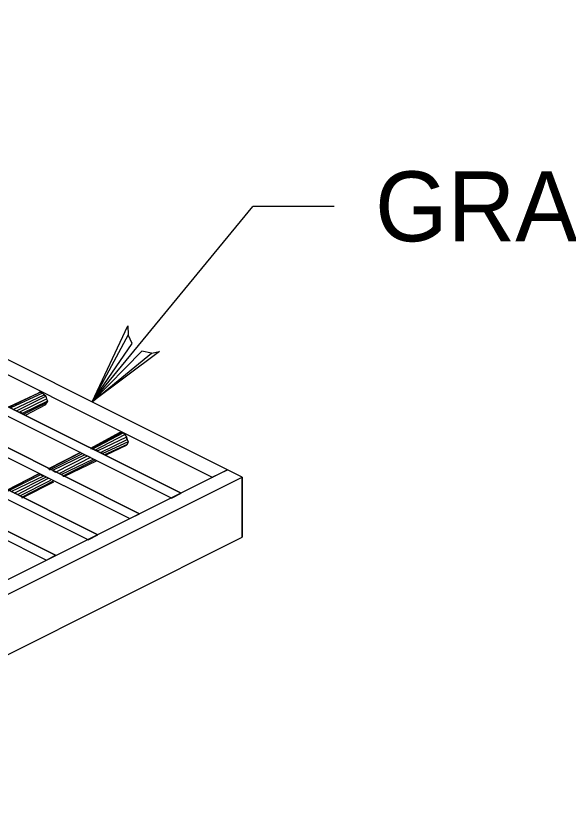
# Model space of a CAD drawing. Extents: x 636183 to 639890, y 299162 to 300538.
# Drawn here: x 636345.94 to 636369.65, y 299233.28 to 299266.83 of the extents above; entities that cross this region are included whole.
import ezdxf

# ---------------------------------------------------------------- set-up
doc = ezdxf.new("R2010")
doc.units = 0
doc.layers.add('Default', color=7, linetype='Continuous')

msp = doc.modelspace()

# ---------------------------------------------------------------- linework, layer by layer
at = {"layer": 'Default'}
for p, q in [((636355.031, 299247.344), (636316.066, 299266.826)), ((636355.031, 299247.344), (636316.066, 299266.826)), ((636315.401, 299266.512), (636354.366, 299247.029)), ((636352.617, 299246.12), (636313.653, 299265.637)), ((636353.037, 299246.33), (636314.072, 299265.812)), ((636314.072, 299265.812), (636353.037, 299246.33)), ((636312.288, 299264.938), (636351.253, 299245.455)), ((636351.253, 299245.455), (636312.288, 299264.938)), ((636311.869, 299264.728), (636350.833, 299245.245)), ((636349.469, 299244.546), (636310.47, 299264.028)), ((636310.47, 299264.028), (636349.469, 299244.546)), ((636349.049, 299244.336), (636310.085, 299263.818)), ((636308.266, 299262.944), (636347.266, 299243.462)), ((636308.686, 299263.154), (636347.65, 299243.671)), ((636347.65, 299243.671), (636308.686, 299263.154)), ((636349.219, 299250.25), (636356.111, 299258.643)), ((636359.609, 299258.643), (636356.111, 299258.643)), ((636346.916, 299250.632), (636345.657, 299250.037)), ((636345.692, 299250.037), (636346.986, 299250.667)), ((636347.091, 299250.632), (636345.727, 299250.002)), ((636345.832, 299249.932), (636347.161, 299250.562)), ((636345.972, 299249.862), (636347.231, 299250.492)), ((636346.986, 299250.667), (636346.916, 299250.632)), ((636346.986, 299250.667), (636347.091, 299250.632)), ((636347.091, 299250.632), (636346.986, 299250.667)), ((636347.161, 299250.562), (636347.091, 299250.632)), ((636347.161, 299250.562), (636347.231, 299250.492)), ((636347.231, 299250.492), (636347.161, 299250.562)), ((636347.231, 299250.492), (636347.266, 299250.387)), ((636346.111, 299249.827), (636347.266, 299250.387)), ((636347.301, 299250.282), (636346.216, 299249.757)), ((636347.266, 299250.212), (636346.286, 299249.722)), ((636346.356, 299249.688), (636347.231, 299250.142)), ((636347.231, 299250.142), (636347.266, 299250.212)), ((636347.266, 299250.387), (636347.301, 299250.282)), ((636347.266, 299250.212), (636347.301, 299250.282)), ((636347.301, 299250.282), (636347.266, 299250.212)), ((636346.216, 299249.757), (636346.111, 299249.827)), ((636346.286, 299249.722), (636346.356, 299249.688)), ((636350.379, 299248.918), (636349.154, 299248.253)), ((636349.189, 299248.253), (636350.449, 299248.918)), ((636349.224, 299248.218), (636350.554, 299248.918)), ((636349.329, 299248.183), (636350.623, 299248.848)), ((636350.449, 299248.918), (636350.379, 299248.918)), ((636350.449, 299248.918), (636350.554, 299248.918)), ((636350.554, 299248.918), (636350.449, 299248.918)), ((636350.554, 299248.918), (636350.623, 299248.848)), ((636350.623, 299248.848), (636350.693, 299248.743)), ((636350.693, 299248.743), (636349.469, 299248.148)), ((636349.574, 299248.079), (636350.728, 299248.638)), ((636350.763, 299248.533), (636349.679, 299248.044)), ((636350.728, 299248.638), (636350.693, 299248.743)), ((636350.693, 299248.743), (636350.728, 299248.638)), ((636350.728, 299248.638), (636350.763, 299248.533)), ((636350.728, 299248.428), (636350.763, 299248.533)), ((636350.763, 299248.533), (636350.728, 299248.428)), ((636349.154, 299248.253), (636349.189, 299248.253)), ((636349.469, 299248.148), (636349.329, 299248.183)), ((636350.728, 299248.428), (636349.749, 299247.974)), ((636349.819, 299247.974), (636350.693, 299248.393)), ((636350.693, 299248.393), (636350.728, 299248.428)), ((636347.336, 299247.379), (636348.7, 299248.079)), ((636348.735, 299248.079), (636347.371, 299247.379)), ((636347.405, 299247.344), (636348.805, 299248.044)), ((636348.91, 299247.974), (636347.511, 299247.309)), ((636347.65, 299247.239), (636349.015, 299247.939)), ((636349.154, 299247.869), (636347.79, 299247.169)), ((636347.895, 299247.134), (636349.259, 299247.799)), ((636348.7, 299248.079), (636348.735, 299248.079)), ((636348.805, 299248.044), (636348.91, 299247.974)), ((636349.015, 299247.939), (636349.154, 299247.869)), ((636349.679, 299248.044), (636349.574, 299248.079)), ((636349.749, 299247.974), (636349.819, 299247.974)), ((636349.364, 299247.764), (636347.965, 299247.064)), ((636348.035, 299247.064), (636349.399, 299247.729)), ((636355.031, 299247.344), (636332.715, 299236.186)), ((636355.031, 299247.344), (636332.715, 299236.186)), ((636345.552, 299246.47), (636346.916, 299247.169)), ((636346.951, 299247.169), (636345.587, 299246.47)), ((636345.622, 299246.435), (636347.021, 299247.134)), ((636346.916, 299247.169), (636346.951, 299247.169)), ((636347.021, 299247.134), (636347.126, 299247.064)), ((636347.371, 299247.379), (636347.405, 299247.344)), ((636347.511, 299247.309), (636347.65, 299247.239)), ((636354.366, 299247.029), (636355.031, 299247.344)), ((636355.66, 299247.029), (636355.031, 299247.344)), ((636333.345, 299235.872), (636355.66, 299247.029)), ((636347.126, 299247.064), (636345.727, 299246.4)), ((636345.867, 299246.33), (636347.231, 299247.029)), ((636347.336, 299246.959), (636346.006, 299246.26)), ((636346.111, 299246.225), (636347.441, 299246.889)), ((636347.545, 299246.854), (636346.181, 299246.155)), ((636346.251, 299246.155), (636347.58, 299246.819)), ((636347.965, 299247.064), (636348.035, 299247.064)), ((636354.366, 299246.994), (636354.366, 299247.029)), ((636354.366, 299247.029), (636354.366, 299246.994)), ((636355.66, 299247.029), (636355.66, 299244.441)), ((636355.66, 299244.441), (636355.66, 299247.029)), ((636346.181, 299246.155), (636346.251, 299246.155)), ((636352.617, 299246.12), (636353.037, 299246.33)), ((636353.037, 299246.33), (636353.037, 299246.33)), ((636350.833, 299245.245), (636351.253, 299245.455)), ((636351.253, 299245.455), (636351.253, 299245.455)), ((636333.345, 299233.283), (636355.66, 299244.441)), ((636349.049, 299244.336), (636349.469, 299244.546)), ((636349.469, 299244.546), (636349.469, 299244.546)), ((636347.266, 299243.462), (636347.65, 299243.671)), ((636347.65, 299243.671), (636347.65, 299243.671))]:
    msp.add_line(p, q, dxfattribs=at)
msp.add_lwpolyline([(636351.762, 299252.343), (636352.106, 299252.409), (636349.219, 299250.25), (636351.762, 299252.343), (636351.35, 299252.428), (636349.219, 299250.25), (636350.941, 299252.756), (636350.767, 299253.135), (636349.219, 299250.25), (636350.75, 299253.514), (636350.767, 299253.135)], dxfattribs=at)

# ---------------------------------------------------------------- texts
msp.add_text('GRATE', height=2.998, dxfattribs=at).set_placement((636361.358, 299257.144))

doc.saveas('drawing.dxf')
